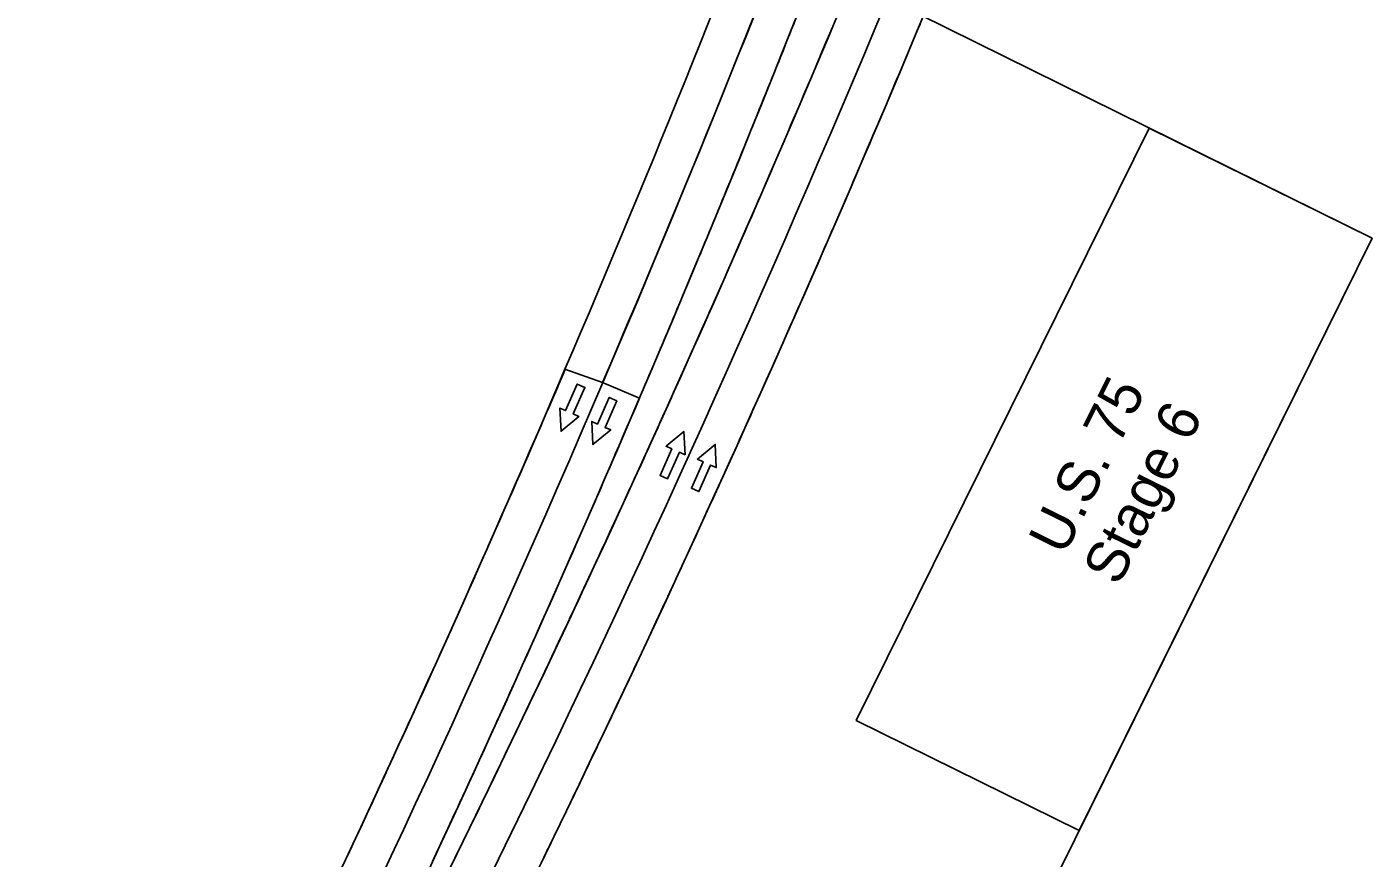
# Model space of a CAD drawing. Extents: x 14090526 to 14125274, y 8637242 to 8677144.
# Drawn here: x 14119604.4 to 14120010, y 8669825.3 to 8670076 of the extents above; entities that cross this region are included whole.
import ezdxf

# ---------------------------------------------------------------- set-up
doc = ezdxf.new("R2010")
doc.units = 0
for name, color, linetype in [('dsnNonPlotable', 7, 'Continuous'), ('dsnPaintExistingBrokenLaneLineWhite', 7, 'Continuous'), ('dsnPaintExistingEdgeLineRightWhite', 7, 'Continuous'), ('dsnShadingPaved', 7, 'Continuous'), ('dsnTextOverlapOdd', 7, 'Continuous'), ('Level 2', 7, 'Continuous'), ('Level 5', 7, 'Continuous')]:
    doc.layers.add(name, color=color, linetype=linetype)

msp = doc.modelspace()

# ---------------------------------------------------------------- linework, layer by layer
at = {"layer": 'dsnNonPlotable'}
msp.add_lwpolyline([(14119315.27, 8668607.09), (14120010, 8670012.23), (14119557.31, 8670236.05), (14118862.58, 8668830.91)], close=True, dxfattribs=at)
at = {"layer": 'dsnPaintExistingBrokenLaneLineWhite'}
for centre, radius, start, end in [((14115416.69, 8671831.7), 4742.58, 332.67082, 339.391), ((14115416.69, 8671831.7), 4754.58, 332.67082, 339.391), ((14115456.71, 8671919.32), 4761.86, 331.51286, 338.23304), ((14115456.71, 8671919.32), 4773.86, 331.51286, 338.23304)]:
    msp.add_arc(centre, radius, start, end, dxfattribs=at)
at = {"layer": 'dsnPaintExistingEdgeLineRightWhite'}
for centre, radius, start, end in [((14115570.48, 8671771.3), 4565.36, 336.7987, 339.3131), ((14115456.71, 8671919.32), 4785.86, 331.51286, 338.23304), ((14115464.82, 8671807.98), 4676.93, 332.66096, 336.89562)]:
    msp.add_arc(centre, radius, start, end, dxfattribs=at)
at = {"layer": 'dsnShadingPaved'}
for p, q in [((14119777.97, 8669968.74), (14119766.62, 8669972.72)), ((14119777.97, 8669968.74), (14119766.62, 8669972.72)), ((14119789.07, 8669964), (14119777.97, 8669968.74)), ((14119777.97, 8669968.74), (14119789.07, 8669964))]:
    msp.add_line(p, q, dxfattribs=at)
for points in [[(14119732.94, 8669824.28), (14119733.44, 8669825.31), (14119735.13, 8669828.76), (14119735.64, 8669829.8), (14119735.82, 8669830.17), (14119737.32, 8669833.24), (14119737.83, 8669834.3), (14119739.5, 8669837.73), (14119739.9, 8669838.54), (14119740.02, 8669838.8), (14119741.68, 8669842.22), (14119742.2, 8669843.3), (14119743.85, 8669846.71), (14119743.95, 8669846.91), (14119744.38, 8669847.8), (14119746.02, 8669851.2), (14119746.56, 8669852.31), (14119748, 8669855.3), (14119748.18, 8669855.69), (14119748.73, 8669856.82), (14119750.34, 8669860.19), (14119750.89, 8669861.33), (14119752.02, 8669863.69), (14119752.5, 8669864.68), (14119753.05, 8669865.84), (14119754.65, 8669869.18), (14119755.21, 8669870.36), (14119756.03, 8669872.09), (14119756.79, 8669873.69), (14119757.36, 8669874.88), (14119758.93, 8669878.19), (14119759.5, 8669879.4), (14119760.03, 8669880.5), (14119761.07, 8669882.7), (14119761.64, 8669883.92), (14119763.2, 8669887.21), (14119763.78, 8669888.45), (14119764, 8669888.91), (14119765.32, 8669891.72), (14119765.91, 8669892.97), (14119767.45, 8669896.23), (14119767.96, 8669897.34), (14119768.04, 8669897.5), (14119769.56, 8669900.75), (14119770.16, 8669902.03), (14119771.67, 8669905.27), (14119771.91, 8669905.77), (14119772.28, 8669906.57), (14119773.78, 8669909.79), (14119774.39, 8669911.1), (14119775.84, 8669914.21), (14119775.88, 8669914.31), (14119776.5, 8669915.64), (14119777.98, 8669918.84), (14119778.6, 8669920.18), (14119779.75, 8669922.66), (14119780.07, 8669923.36), (14119780.7, 8669924.73), (14119782.16, 8669927.89), (14119782.8, 8669929.27), (14119783.64, 8669931.11), (14119784.24, 8669932.42), (14119784.89, 8669933.82), (14119786.32, 8669936.96), (14119786.97, 8669938.37), (14119787.52, 8669939.57), (14119788.4, 8669941.49), (14119789.05, 8669942.92), (14119790.47, 8669946.03), (14119791.12, 8669947.48), (14119791.38, 8669948.04), (14119792.53, 8669950.57), (14119793.19, 8669952.03), (14119794.59, 8669955.11), (14119795.26, 8669956.59), (14119796.65, 8669959.66), (14119797.32, 8669961.15), (14119798.7, 8669964.21), (14119799.06, 8669965.01), (14119799.37, 8669965.71), (14119800.74, 8669968.75), (14119801.43, 8669970.28), (14119802.78, 8669973.31), (14119802.87, 8669973.5), (14119803.47, 8669974.85), (14119804.82, 8669977.86), (14119805.51, 8669979.42), (14119806.67, 8669982.01), (14119806.85, 8669982.41), (14119807.55, 8669983.99), (14119808.87, 8669986.97), (14119809.58, 8669988.56), (14119810.45, 8669990.51), (14119810.9, 8669991.53), (14119811.61, 8669993.14), (14119812.91, 8669996.09), (14119813.63, 8669997.72), (14119814.21, 8669999.03), (14119814.92, 8670000.65), (14119815.65, 8670002.3), (14119816.93, 8670005.22), (14119817.66, 8670006.88), (14119817.96, 8670007.55), (14119818.93, 8670009.79), (14119819.67, 8670011.47), (14119820.93, 8670014.36), (14119821.67, 8670016.06), (14119822.92, 8670018.93), (14119823.67, 8670020.64), (14119824.28, 8670022.04), (14119824.91, 8670023.5), (14119825.4, 8670024.62), (14119825.66, 8670025.24), (14119826.9, 8670028.08), (14119827.65, 8670029.83), (14119828.87, 8670032.66), (14119829.1, 8670033.17), (14119829.64, 8670034.42), (14119830.85, 8670037.24), (14119831.62, 8670039.02), (14119832.78, 8670041.73), (14119832.82, 8670041.82), (14119833.59, 8670043.62), (14119834.78, 8670046.41), (14119835.56, 8670048.23), (14119836.44, 8670050.29), (14119836.74, 8670050.99), (14119837.52, 8670052.83), (14119838.69, 8670055.58), (14119839.48, 8670057.44), (14119840.09, 8670058.85), (14119840.64, 8670060.17), (14119841.44, 8670062.04), (14119842.59, 8670064.76), (14119843.39, 8670066.66), (14119843.71, 8670067.43), (14119844.53, 8670069.36), (14119845.33, 8670071.27), (14119846.46, 8670073.95), (14119847.27, 8670075.88), (14119847.33, 8670076.01)], [(14119847.33, 8670076.01), (14119847.27, 8670075.88), (14119846.46, 8670073.95), (14119845.33, 8670071.27), (14119844.53, 8670069.36), (14119843.71, 8670067.43), (14119843.39, 8670066.66), (14119842.59, 8670064.76), (14119841.44, 8670062.04), (14119840.64, 8670060.17), (14119840.09, 8670058.85), (14119839.48, 8670057.44), (14119838.69, 8670055.58), (14119837.52, 8670052.83), (14119836.74, 8670050.99), (14119836.44, 8670050.29), (14119835.56, 8670048.23), (14119834.78, 8670046.41), (14119833.59, 8670043.62), (14119832.82, 8670041.82), (14119832.78, 8670041.73), (14119831.62, 8670039.02), (14119830.85, 8670037.24), (14119829.64, 8670034.42), (14119829.1, 8670033.17), (14119828.87, 8670032.66), (14119827.65, 8670029.83), (14119826.9, 8670028.08), (14119825.66, 8670025.24), (14119825.4, 8670024.62), (14119824.91, 8670023.5), (14119824.28, 8670022.04), (14119823.67, 8670020.64), (14119822.92, 8670018.93), (14119821.67, 8670016.06), (14119820.93, 8670014.36), (14119819.67, 8670011.47), (14119818.93, 8670009.79), (14119817.96, 8670007.55), (14119817.66, 8670006.88), (14119816.93, 8670005.22), (14119815.65, 8670002.3), (14119814.92, 8670000.65), (14119814.21, 8669999.03), (14119813.63, 8669997.72), (14119812.91, 8669996.09), (14119811.61, 8669993.14), (14119810.9, 8669991.53), (14119810.45, 8669990.51), (14119809.58, 8669988.56), (14119808.87, 8669986.97), (14119807.55, 8669983.99), (14119806.85, 8669982.41), (14119806.67, 8669982.01), (14119805.51, 8669979.42), (14119804.82, 8669977.86), (14119803.47, 8669974.85), (14119802.87, 8669973.5), (14119802.78, 8669973.31), (14119801.43, 8669970.28), (14119800.74, 8669968.75), (14119799.37, 8669965.71), (14119799.06, 8669965.01), (14119798.7, 8669964.21), (14119797.32, 8669961.15), (14119796.65, 8669959.66), (14119795.26, 8669956.59), (14119794.59, 8669955.11), (14119793.19, 8669952.03), (14119792.53, 8669950.57), (14119791.38, 8669948.04), (14119791.12, 8669947.48), (14119790.47, 8669946.03), (14119789.05, 8669942.92), (14119788.4, 8669941.49), (14119787.52, 8669939.57), (14119786.97, 8669938.37), (14119786.32, 8669936.96), (14119784.89, 8669933.82), (14119784.24, 8669932.42), (14119783.64, 8669931.11), (14119782.8, 8669929.27), (14119782.16, 8669927.89), (14119780.7, 8669924.73), (14119780.07, 8669923.36), (14119779.75, 8669922.66), (14119778.6, 8669920.18), (14119777.98, 8669918.84), (14119776.5, 8669915.64), (14119775.88, 8669914.31), (14119775.84, 8669914.21), (14119774.39, 8669911.1), (14119773.78, 8669909.79), (14119772.28, 8669906.57), (14119771.91, 8669905.77), (14119771.67, 8669905.27), (14119770.16, 8669902.03), (14119769.56, 8669900.75), (14119768.04, 8669897.5), (14119767.96, 8669897.34), (14119767.45, 8669896.23), (14119765.91, 8669892.97), (14119765.32, 8669891.72), (14119764, 8669888.91), (14119763.78, 8669888.45), (14119763.2, 8669887.21), (14119761.64, 8669883.92), (14119761.07, 8669882.7), (14119760.03, 8669880.5), (14119759.5, 8669879.4), (14119758.93, 8669878.19), (14119757.36, 8669874.88), (14119756.79, 8669873.69), (14119756.03, 8669872.09), (14119755.21, 8669870.36), (14119754.65, 8669869.18), (14119753.05, 8669865.84), (14119752.5, 8669864.68), (14119752.02, 8669863.69), (14119750.89, 8669861.33), (14119750.34, 8669860.19), (14119748.73, 8669856.82), (14119748.18, 8669855.69), (14119748, 8669855.3), (14119746.56, 8669852.31), (14119746.02, 8669851.2), (14119744.38, 8669847.8), (14119743.95, 8669846.91), (14119743.85, 8669846.71), (14119742.2, 8669843.3), (14119741.68, 8669842.22), (14119740.02, 8669838.8), (14119739.9, 8669838.54), (14119739.5, 8669837.73), (14119737.83, 8669834.3), (14119737.32, 8669833.24), (14119735.82, 8669830.17), (14119735.64, 8669829.8), (14119735.13, 8669828.76), (14119733.44, 8669825.31), (14119732.94, 8669824.28)], [(14119873.68, 8670076.81), (14119873.29, 8670075.87), (14119873.07, 8670075.36), (14119872.46, 8670073.9), (14119871.35, 8670071.23), (14119870.53, 8670069.28), (14119869.46, 8670066.72), (14119869.4, 8670066.59), (14119868.59, 8670064.65), (14119867.45, 8670061.95), (14119866.64, 8670060.03), (14119865.83, 8670058.1), (14119865.5, 8670057.32), (14119864.69, 8670055.42), (14119863.54, 8670052.68), (14119862.74, 8670050.8), (14119862.18, 8670049.48), (14119861.57, 8670048.05), (14119860.78, 8670046.19), (14119859.6, 8670043.42), (14119858.82, 8670041.58), (14119858.51, 8670040.86), (14119857.63, 8670038.8), (14119856.85, 8670036.96), (14119855.65, 8670034.17), (14119854.87, 8670032.36), (14119854.83, 8670032.26), (14119853.67, 8670029.55), (14119852.89, 8670027.75), (14119851.68, 8670024.93), (14119851.13, 8670023.67), (14119850.91, 8670023.15), (14119849.68, 8670020.31), (14119848.92, 8670018.55), (14119847.68, 8670015.69), (14119847.42, 8670015.07), (14119846.93, 8670013.95), (14119846.29, 8670012.48), (14119845.68, 8670011.07), (14119844.93, 8670009.35), (14119843.67, 8670006.46), (14119842.93, 8670004.76), (14119841.66, 8670001.85), (14119840.92, 8670000.16), (14119839.94, 8669997.92), (14119839.64, 8669997.24), (14119838.91, 8669995.57), (14119837.62, 8669992.64), (14119836.89, 8669990.98), (14119836.17, 8669989.35), (14119835.59, 8669988.03), (14119834.87, 8669986.4), (14119833.56, 8669983.43), (14119832.84, 8669981.81), (14119832.39, 8669980.79), (14119831.52, 8669978.83), (14119830.81, 8669977.23), (14119829.48, 8669974.24), (14119828.77, 8669972.65), (14119828.59, 8669972.24), (14119827.43, 8669969.64), (14119826.73, 8669968.07), (14119825.38, 8669965.05), (14119824.78, 8669963.7), (14119824.68, 8669963.49), (14119823.32, 8669960.46), (14119822.63, 8669958.92), (14119821.26, 8669955.87), (14119820.94, 8669955.16), (14119820.58, 8669954.35), (14119819.2, 8669951.28), (14119818.52, 8669949.78), (14119817.13, 8669946.7), (14119816.45, 8669945.21), (14119815.05, 8669942.12), (14119814.38, 8669940.65), (14119813.23, 8669938.11), (14119812.97, 8669937.54), (14119812.31, 8669936.08), (14119810.89, 8669932.96), (14119810.23, 8669931.52), (14119809.35, 8669929.6), (14119808.79, 8669928.39), (14119808.14, 8669926.96), (14119806.7, 8669923.81), (14119806.06, 8669922.41), (14119805.45, 8669921.09), (14119804.6, 8669919.24), (14119803.96, 8669917.85), (14119802.5, 8669914.68), (14119801.86, 8669913.3), (14119801.54, 8669912.59), (14119800.39, 8669910.11), (14119799.76, 8669908.75), (14119798.27, 8669905.55), (14119797.65, 8669904.21), (14119797.6, 8669904.1), (14119796.16, 8669900.98), (14119795.54, 8669899.66), (14119794.03, 8669896.43), (14119793.66, 8669895.62), (14119793.42, 8669895.11), (14119791.9, 8669891.87), (14119791.3, 8669890.57), (14119789.77, 8669887.31), (14119789.69, 8669887.15), (14119789.17, 8669886.04), (14119787.63, 8669882.76), (14119787.04, 8669881.5), (14119785.71, 8669878.68), (14119785.49, 8669878.21), (14119784.9, 8669876.96), (14119783.34, 8669873.66), (14119782.76, 8669872.43), (14119781.72, 8669870.22), (14119781.19, 8669869.12), (14119780.61, 8669867.9), (14119779.03, 8669864.57), (14119778.46, 8669863.38), (14119777.7, 8669861.77), (14119776.87, 8669860.03), (14119776.31, 8669858.85), (14119774.71, 8669855.5), (14119774.15, 8669854.33), (14119773.67, 8669853.33), (14119772.54, 8669850.96), (14119771.98, 8669849.81), (14119770.36, 8669846.43), (14119769.81, 8669845.29), (14119769.62, 8669844.89), (14119768.18, 8669841.89), (14119767.64, 8669840.77), (14119765.99, 8669837.37), (14119765.56, 8669836.47), (14119765.46, 8669836.26), (14119763.8, 8669832.84), (14119763.27, 8669831.74), (14119761.61, 8669828.31), (14119761.48, 8669828.05), (14119761.09, 8669827.23), (14119759.41, 8669823.79)], [(14119766.69, 8669972.69), (14119765.79, 8669970.59), (14119765.29, 8669969.44), (14119763.82, 8669966.01), (14119763.36, 8669964.94), (14119761.85, 8669961.42), (14119761.65, 8669960.94), (14119761.4, 8669960.37), (14119759.88, 8669956.84), (14119759.43, 8669955.81), (14119757.98, 8669952.45), (14119757.9, 8669952.27), (14119757.46, 8669951.25), (14119755.92, 8669947.69), (14119755.48, 8669946.69), (14119754.3, 8669943.97), (14119753.93, 8669943.12), (14119753.5, 8669942.13), (14119751.93, 8669938.55), (14119751.51, 8669937.57), (14119750.6, 8669935.5), (14119749.94, 8669933.98), (14119749.52, 8669933.02), (14119747.93, 8669929.41), (14119747.52, 8669928.47), (14119746.89, 8669927.03), (14119745.92, 8669924.84), (14119745.52, 8669923.92), (14119743.91, 8669920.28), (14119743.51, 8669919.37), (14119743.15, 8669918.57), (14119741.89, 8669915.72), (14119741.5, 8669914.82), (14119739.87, 8669911.16), (14119739.48, 8669910.28), (14119739.41, 8669910.12), (14119737.84, 8669906.6), (14119737.46, 8669905.74), (14119735.81, 8669902.05), (14119735.64, 8669901.67), (14119735.43, 8669901.2), (14119733.77, 8669897.5), (14119733.4, 8669896.66), (14119731.86, 8669893.23), (14119731.73, 8669892.95), (14119731.36, 8669892.13), (14119729.69, 8669888.4), (14119729.32, 8669887.59), (14119728.06, 8669884.8), (14119727.64, 8669883.85), (14119727.28, 8669883.06), (14119725.58, 8669879.31), (14119725.23, 8669878.53), (14119724.25, 8669876.37), (14119723.52, 8669874.77), (14119723.17, 8669874.01), (14119721.45, 8669870.23), (14119721.11, 8669869.48), (14119720.42, 8669867.96), (14119719.38, 8669865.69), (14119719.05, 8669864.96), (14119717.31, 8669861.15), (14119716.98, 8669860.44), (14119716.57, 8669859.55), (14119715.23, 8669856.62), (14119714.91, 8669855.92), (14119713.14, 8669852.09), (14119712.83, 8669851.4), (14119712.71, 8669851.14), (14119711.05, 8669847.56), (14119710.74, 8669846.89), (14119708.96, 8669843.04), (14119708.65, 8669842.38), (14119706.86, 8669838.51), (14119706.56, 8669837.87), (14119704.93, 8669834.36), (14119704.76, 8669833.99), (14119704.46, 8669833.36), (14119702.65, 8669829.47), (14119702.36, 8669828.85), (14119701.01, 8669825.98), (14119700.54, 8669824.95)], [(14119726.68, 8669824.23), (14119728.32, 8669827.75), (14119728.63, 8669828.4), (14119730.43, 8669832.28), (14119730.74, 8669832.95), (14119732.53, 8669836.82), (14119732.84, 8669837.5), (14119734.5, 8669841.09), (14119734.62, 8669841.36), (14119734.94, 8669842.05), (14119736.71, 8669845.89), (14119737.04, 8669846.6), (14119738.38, 8669849.54), (14119738.8, 8669850.44), (14119739.13, 8669851.16), (14119740.87, 8669854.98), (14119741.21, 8669855.72), (14119742.25, 8669857.99), (14119742.95, 8669859.52), (14119743.29, 8669860.28), (14119745.02, 8669864.07), (14119745.37, 8669864.84), (14119746.1, 8669866.45), (14119747.09, 8669868.62), (14119747.44, 8669869.41), (14119749.15, 8669873.17), (14119749.51, 8669873.97), (14119749.94, 8669874.92), (14119751.2, 8669877.73), (14119751.57, 8669878.54), (14119753.25, 8669882.28), (14119753.63, 8669883.11), (14119753.75, 8669883.4), (14119755.3, 8669886.84), (14119755.68, 8669887.69), (14119757.34, 8669891.4), (14119757.55, 8669891.88), (14119757.73, 8669892.26), (14119759.38, 8669895.96), (14119759.77, 8669896.84), (14119761.34, 8669900.36), (14119761.41, 8669900.53), (14119761.81, 8669901.42), (14119763.44, 8669905.1), (14119763.84, 8669906), (14119765.1, 8669908.86), (14119765.46, 8669909.67), (14119765.87, 8669910.59), (14119767.48, 8669914.24), (14119767.89, 8669915.17), (14119768.85, 8669917.37), (14119769.49, 8669918.81), (14119769.91, 8669919.76), (14119771.5, 8669923.38), (14119771.92, 8669924.35), (14119772.59, 8669925.88), (14119773.5, 8669927.96), (14119773.93, 8669928.94), (14119775.5, 8669932.54), (14119775.93, 8669933.54), (14119776.31, 8669934.4), (14119777.49, 8669937.12), (14119777.93, 8669938.14), (14119779.48, 8669941.7), (14119779.92, 8669942.73), (14119780.01, 8669942.92), (14119781.46, 8669946.29), (14119781.91, 8669947.34), (14119783.44, 8669950.88), (14119783.69, 8669951.45), (14119783.9, 8669951.94), (14119785.41, 8669955.47), (14119785.88, 8669956.54), (14119787.35, 8669959.99), (14119787.85, 8669961.15), (14119789.07, 8669964)], [(14119726.68, 8669824.23), (14119728.32, 8669827.75), (14119728.63, 8669828.4), (14119730.43, 8669832.28), (14119730.74, 8669832.95), (14119732.53, 8669836.82), (14119732.84, 8669837.5), (14119734.5, 8669841.09), (14119734.62, 8669841.36), (14119734.94, 8669842.05), (14119736.71, 8669845.89), (14119737.04, 8669846.6), (14119738.38, 8669849.54), (14119738.8, 8669850.44), (14119739.13, 8669851.16), (14119740.87, 8669854.98), (14119741.21, 8669855.72), (14119742.25, 8669857.99), (14119742.95, 8669859.52), (14119743.29, 8669860.28), (14119745.02, 8669864.07), (14119745.37, 8669864.84), (14119746.1, 8669866.45), (14119747.09, 8669868.62), (14119747.44, 8669869.41), (14119749.15, 8669873.17), (14119749.51, 8669873.97), (14119749.94, 8669874.92), (14119751.2, 8669877.73), (14119751.57, 8669878.54), (14119753.25, 8669882.28), (14119753.63, 8669883.11), (14119753.75, 8669883.4), (14119755.3, 8669886.84), (14119755.68, 8669887.69), (14119757.34, 8669891.4), (14119757.55, 8669891.88), (14119757.73, 8669892.26), (14119759.38, 8669895.96), (14119759.77, 8669896.84), (14119761.34, 8669900.36), (14119761.41, 8669900.53), (14119761.81, 8669901.42), (14119763.44, 8669905.1), (14119763.84, 8669906), (14119765.1, 8669908.86), (14119765.46, 8669909.67), (14119765.87, 8669910.59), (14119767.48, 8669914.24), (14119767.89, 8669915.17), (14119768.85, 8669917.37), (14119769.49, 8669918.81), (14119769.91, 8669919.76), (14119771.5, 8669923.38), (14119771.92, 8669924.35), (14119772.59, 8669925.88), (14119773.5, 8669927.96), (14119773.93, 8669928.94), (14119775.5, 8669932.54), (14119775.93, 8669933.54), (14119776.31, 8669934.4), (14119777.49, 8669937.12), (14119777.93, 8669938.14), (14119779.48, 8669941.7), (14119779.92, 8669942.73), (14119780.01, 8669942.92), (14119781.46, 8669946.29), (14119781.91, 8669947.34), (14119783.44, 8669950.88), (14119783.69, 8669951.45), (14119783.9, 8669951.94), (14119785.41, 8669955.47), (14119785.88, 8669956.54), (14119787.35, 8669959.99), (14119787.85, 8669961.15), (14119789.07, 8669964)]]:
    msp.add_lwpolyline(points, dxfattribs=at)
for radius, start in [(4565.36, 336.7987), (4577.36, 336.80891), (4577.36, 336.80891)]:
    msp.add_arc((14115570.48, 8671771.3), radius, start, 339.3131, dxfattribs=at)
msp.add_open_spline([(14119789.07, 8669964), (14119790.92, 8669968.32), (14119796.39, 8669981.2), (14119805.42, 8670002.67), (14119816.06, 8670028.43), (14119826.56, 8670054.25), (14119836.9, 8670080.13), (14119847.09, 8670106.08), (14119857.14, 8670132.07), (14119863.71, 8670149.45), (14119866.99, 8670158.14)], degree=3, dxfattribs=at)
msp.add_open_spline([(14119789.07, 8669964), (14119790.92, 8669968.32), (14119796.39, 8669981.2), (14119805.42, 8670002.67), (14119816.06, 8670028.43), (14119826.56, 8670054.25), (14119836.9, 8670080.13), (14119847.09, 8670106.08), (14119857.14, 8670132.07), (14119863.71, 8670149.45), (14119866.99, 8670158.14)], degree=3, dxfattribs=at)
at = {"layer": 'dsnTextOverlapOdd'}
for points in [[(14120010, 8670012.23), (14119921.68, 8669833.59), (14119854.45, 8669866.83), (14119942.77, 8670045.47)], [(14119854.45, 8669866.83), (14119942.77, 8670045.47), (14120010, 8670012.23), (14119921.68, 8669833.59)]]:
    msp.add_lwpolyline(points, close=True, dxfattribs=at)
at = {"layer": 'Level 2'}
for points in [[(14119772.63, 8669967.25), (14119770.34, 8669968.26), (14119766.81, 8669960.26), (14119765.09, 8669961.02), (14119765.43, 8669954.04), (14119770.81, 8669958.49), (14119769.1, 8669959.25)], [(14119782.24, 8669963.21), (14119779.96, 8669964.22), (14119776.42, 8669956.22), (14119774.71, 8669956.98), (14119775.04, 8669950), (14119780.42, 8669954.45), (14119778.71, 8669955.21)], [(14119795.3, 8669940.73), (14119797.59, 8669939.72), (14119801.13, 8669947.72), (14119802.84, 8669946.96), (14119802.51, 8669953.94), (14119797.13, 8669949.49), (14119798.84, 8669948.73)], [(14119804.73, 8669936.86), (14119807.01, 8669935.85), (14119810.55, 8669943.85), (14119812.26, 8669943.09), (14119811.93, 8669950.07), (14119806.55, 8669945.62), (14119808.26, 8669944.86)]]:
    msp.add_lwpolyline(points, close=True, dxfattribs=at)
at = {"layer": 'Level 5'}
for points in [[(14119769.1, 8669959.25), (14119770.81, 8669958.49), (14119765.43, 8669954.04), (14119765.09, 8669961.02), (14119766.81, 8669960.26), (14119770.34, 8669968.26), (14119772.63, 8669967.25), (14119769.1, 8669959.25)], [(14119778.71, 8669955.21), (14119780.42, 8669954.45), (14119775.04, 8669950), (14119774.71, 8669956.98), (14119776.42, 8669956.22), (14119779.96, 8669964.22), (14119782.24, 8669963.21), (14119778.71, 8669955.21)], [(14119798.84, 8669948.73), (14119797.13, 8669949.49), (14119802.51, 8669953.94), (14119802.84, 8669946.96), (14119801.13, 8669947.72), (14119797.59, 8669939.72), (14119795.3, 8669940.73), (14119798.84, 8669948.73)], [(14119808.26, 8669944.86), (14119806.55, 8669945.62), (14119811.93, 8669950.07), (14119812.26, 8669943.09), (14119810.55, 8669943.85), (14119807.01, 8669935.85), (14119804.73, 8669936.86), (14119808.26, 8669944.86)]]:
    msp.add_lwpolyline(points, dxfattribs=at)

# ---------------------------------------------------------------- texts
at = {"layer": 'dsnTextOverlapOdd'}
for s, p in [('U.S. 75', (14119917.19, 8669916.18)), ('Stage 6', (14119933.58, 8669907.01))]:
    msp.add_text(s, height=12.5, rotation=63.6912, dxfattribs=at).set_placement(p)

doc.saveas('drawing.dxf')
